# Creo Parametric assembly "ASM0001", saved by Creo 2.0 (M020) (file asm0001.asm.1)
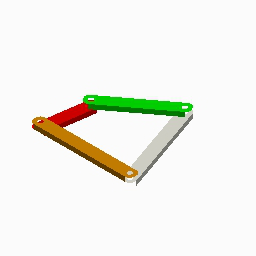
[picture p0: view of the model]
Units: Inch lbm Second (Pro/E Default); INCH, POUND, SECS

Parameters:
  MENU = "list"

Other parameters: FIXBAR, CRANK, ROCKER, ROCKER2, D2

Created from: INLBS_ASM_DESIGN.ASM

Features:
  1. datum plane "ASM_RIGHT"
  2. datum plane "ASM_TOP"
  3. datum plane "ASM_FRONT"
  4. coordinate system
  5. component "LINK0"
  6. component "LINK1"
  7. component "LINK2"
  8. component "LINK3"

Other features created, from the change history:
  component "LINK0.PRT"
  component "LINK1.PRT"
  component "LINK2.PRT"
  component "LINK3.PRT"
